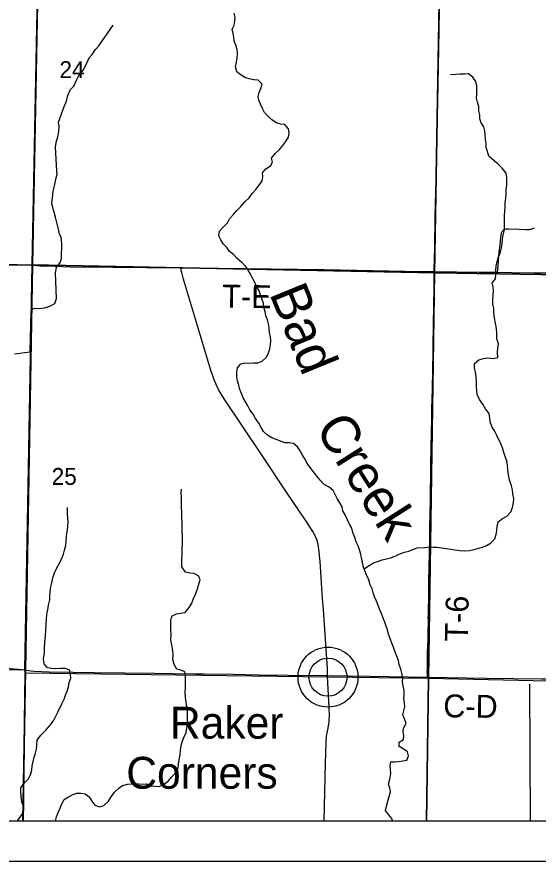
# Model space of a CAD drawing. Extents: x 0 to 42, y 0 to 22.
# Drawn here: x 6.167 to 7.46, y 14 to 16.093 of the extents above; entities that cross this region are included whole.
import ezdxf

# ---------------------------------------------------------------- set-up
doc = ezdxf.new("R2010")
doc.units = 0
for name, color, linetype in [('Default', 7, 'Continuous'), ('GM_X_County_Road', 7, 'Continuous'), ('GM_X_County_Road_Text', 7, 'Continuous'), ('GM_X_Interchange_Ramps', 7, 'Continuous'), ('GM_X_Minor_River', 7, 'Continuous'), ('GM_X_Minor_River_Text', 7, 'Continuous'), ('GM_X_Section', 7, 'Continuous'), ('GM_X_Section_Text', 7, 'Continuous'), ('GM_X_Township_Road', 7, 'Continuous'), ('GM_X_Township_Road_Text', 7, 'Continuous'), ('GM_X_Unincorporated', 7, 'Continuous'), ('GM_X_Unincorporated_Location', 7, 'Continuous'), ('GM_X_Unincorporated_Text', 7, 'Continuous'), ('SH_Data', 7, 'Continuous')]:
    doc.layers.add(name, color=color, linetype=linetype)

msp = doc.modelspace()

# ---------------------------------------------------------------- linework, layer by layer
at = {"layer": 'Default'}
for points in [[(5.1749, 14.1), (6.1826, 14.1), (6.1876, 14.466), (6.1871, 14.4739), (5.1819, 14.4731)], [(6.1826, 14.1), (7.1834, 14.1), (7.1882, 14.4532), (6.1876, 14.466)], [(7.1834, 14.1), (8.1861, 14.1), (8.1913, 14.4319), (7.6712, 14.4424), (7.1882, 14.4532)]]:
    msp.add_lwpolyline(points, close=True, dxfattribs=at)
at = {"layer": 'GM_X_County_Road'}
for points in [[(6.0728, 15.481), (6.1062, 15.4808), (6.131, 15.4805), (6.1684, 15.4792), (6.2065, 15.4773)], [(6.2065, 15.4773), (6.2244, 15.4764), (6.2618, 15.475), (6.2992, 15.4739), (6.4052, 15.4729), (6.5744, 15.4712)], [(6.9382, 14.4599), (6.9375, 14.4779), (6.929, 14.6113), (6.9272, 14.6338), (6.9258, 14.65), (6.9197, 14.743), (6.9165, 14.7739), (6.9144, 14.786), (6.911, 14.7978), (6.9076, 14.8064), (6.9017, 14.8172), (6.8849, 14.8433), (6.8674, 14.8689), (6.8375, 14.9124), (6.7738, 15.0082), (6.6818, 15.1465), (6.6686, 15.1676), (6.6614, 15.1815), (6.6567, 15.193), (6.648, 15.2197), (6.5806, 15.4428), (6.5761, 15.4592), (6.5749, 15.4635), (6.5747, 15.4653), (6.5745, 15.4671), (6.5744, 15.4692), (6.5744, 15.4712)], [(5.9383, 14.4777), (6.0367, 14.4782), (6.1238, 14.4786), (6.1393, 14.4782), (6.1611, 14.4767), (6.1797, 14.4748), (6.1885, 14.4738)], [(6.1885, 14.4738), (6.2105, 14.4714), (6.2291, 14.4699), (6.2477, 14.4692), (6.3067, 14.4683), (6.3596, 14.4677), (6.5087, 14.4658), (6.5554, 14.4655), (6.6113, 14.4646), (6.633, 14.464), (6.7045, 14.4632), (6.7667, 14.4623), (6.8413, 14.4611), (6.9345, 14.46), (6.9382, 14.4599)], [(6.93, 14.1), (6.9307, 14.1363), (6.933, 14.2418), (6.9345, 14.2936), (6.9348, 14.3009), (6.9351, 14.3058), (6.9355, 14.3095), (6.9385, 14.3252), (6.9414, 14.3398), (6.942, 14.3453), (6.9424, 14.3505), (6.9425, 14.3591), (6.9419, 14.3808), (6.9388, 14.4417), (6.9382, 14.4599)], [(6.9382, 14.4599), (7.0431, 14.4582), (7.1857, 14.4561)], [(7.1857, 14.4561), (7.2357, 14.4554), (7.3321, 14.4538), (7.4004, 14.4526), (7.4687, 14.4518), (7.478, 14.4516), (7.4904, 14.4511), (7.5991, 14.4495), (7.6551, 14.4487), (7.6695, 14.4487)]]:
    msp.add_lwpolyline(points, dxfattribs=at)
at = {"layer": 'GM_X_Interchange_Ramps'}
for points in [[(2.1, 18.5138), (2.1, 14.1), (6.182, 14.1), (6.1883, 14.4744), (6.2063, 15.4779), (6.2205, 16.2146)], [(6.2205, 16.2146), (6.2063, 15.4779), (6.1883, 14.4744), (6.182, 14.1), (8.9, 14.1), (8.9, 18.4589)]]:
    msp.add_lwpolyline(points, dxfattribs=at)
at = {"layer": 'GM_X_Minor_River'}
msp.add_line((7.4413, 14.1), (7.4401, 14.4386), dxfattribs=at)
for points in [[(6.6685, 15.5504), (6.6702, 15.5617), (6.6791, 15.5722), (6.6896, 15.5826), (6.6951, 15.5928), (6.704, 15.6028), (6.7125, 15.6125), (6.723, 15.623), (6.733, 15.6345), (6.7435, 15.6449), (6.7513, 15.655), (6.7598, 15.6651), (6.7683, 15.676), (6.7758, 15.6868), (6.7771, 15.697), (6.7769, 15.7065), (6.7847, 15.7166), (6.7962, 15.7236), (6.8013, 15.7334), (6.7992, 15.7429), (6.8078, 15.7545), (6.819, 15.7642), (6.8271, 15.7743), (6.8349, 15.7843), (6.8408, 15.7952), (6.8429, 15.8058), (6.8408, 15.8157), (6.8323, 15.8265), (6.8221, 15.8275), (6.8112, 15.8308), (6.7996, 15.8382), (6.7896, 15.8468), (6.7818, 15.8564), (6.7767, 15.8664), (6.7716, 15.8771), (6.7676, 15.8867), (6.7659, 15.8962), (6.7684, 15.9061), (6.7728, 15.9158), (6.776, 15.9264), (6.766, 15.9361), (6.755, 15.9375), (6.7433, 15.94), (6.7331, 15.9432), (6.7234, 15.9491), (6.7133, 15.9573), (6.7094, 15.9695), (6.7119, 15.9812), (6.714, 15.9911), (6.7146, 16.0024), (6.7141, 16.0127), (6.7101, 16.0234), (6.7061, 16.033), (6.7052, 16.0429), (6.7035, 16.0524), (6.7014, 16.0627), (6.7062, 16.0729), (6.7083, 16.0831), (6.7088, 16.0925), (6.706, 16.1025)], [(6.1613, 15.2576), (6.2001, 15.2625), (6.2029, 15.3638), (6.2045, 15.3683), (6.2129, 15.3712), (6.2228, 15.3706), (6.2357, 15.3715), (6.2494, 15.3758), (6.2616, 15.3824), (6.2653, 15.3948), (6.2628, 15.4583), (6.2653, 15.4715), (6.2747, 15.4839), (6.2779, 15.4945), (6.2786, 15.5313), (6.2771, 15.5473), (6.2727, 15.5542), (6.2706, 15.5671), (6.2675, 15.5801), (6.2633, 15.5965), (6.2586, 15.6114), (6.2541, 15.6301), (6.2577, 15.6612), (6.261, 15.6744), (6.264, 15.691), (6.2673, 15.7031), (6.2667, 15.7104), (6.265, 15.7411), (6.263, 15.7704), (6.2647, 15.7818), (6.2688, 15.7961), (6.2713, 15.8094), (6.2719, 15.8215), (6.2703, 15.8322), (6.2847, 15.8714), (6.2906, 15.8845), (6.2939, 15.8981), (6.3003, 15.9132), (6.3088, 15.9218), (6.3155, 15.9364), (6.3207, 15.9481), (6.3316, 15.9612), (6.3398, 15.977), (6.3466, 15.992), (6.3543, 16.0002), (6.3621, 16.0122), (6.3703, 16.0219), (6.4058, 16.0728)], [(7.3735, 15.5521), (7.3764, 15.5619), (7.3766, 15.573), (7.3772, 15.5874), (7.3771, 15.6003), (7.3781, 15.6105), (7.3787, 15.6215), (7.3782, 15.6333), (7.3799, 15.6431), (7.3809, 15.6549), (7.3814, 15.6647), (7.3824, 15.6757), (7.3826, 15.6856), (7.3824, 15.6951), (7.3807, 15.7058), (7.3711, 15.7181), (7.3615, 15.7278), (7.3514, 15.7364), (7.3384, 15.748), (7.3345, 15.7595), (7.3316, 15.7698), (7.3318, 15.7797), (7.3301, 15.7896), (7.3289, 15.801), (7.3283, 15.8105), (7.3255, 15.8204), (7.3188, 15.8304), (7.3156, 15.8407), (7.3155, 15.8506), (7.3134, 15.8601), (7.3132, 15.8712), (7.31, 15.8815), (7.3079, 15.8918), (7.3085, 15.902), (7.308, 15.9115), (7.3082, 15.9225), (7.3057, 15.9328), (7.2984, 15.944), (7.2876, 15.9522), (7.2777, 15.9509), (7.2667, 15.9511), (7.2561, 15.9505), (7.2466, 15.95), (7.2428, 15.9508)], [(7.072, 14.6138), (7.0677, 14.6234), (7.0634, 14.6341), (7.0594, 14.6449), (7.0547, 14.6552), (7.0515, 14.6651), (7.0483, 14.6755), (7.0436, 14.6854), (7.04, 14.6973), (7.035, 14.7099), (7.0306, 14.7195), (7.0267, 14.7313), (7.0246, 14.742), (7.0225, 14.7515), (7.0208, 14.7614), (7.0176, 14.7718), (7.014, 14.7817), (7.0089, 14.7913), (7.0058, 14.8028), (7.0003, 14.8146), (6.9979, 14.8253), (6.9928, 14.8353), (6.9877, 14.846), (6.9815, 14.8583), (6.9756, 14.8683), (6.9739, 14.8782), (6.9681, 14.8882), (6.9622, 14.8989), (6.9568, 14.9093), (6.952, 14.9193), (6.9416, 14.9275), (6.9296, 14.9342), (6.9196, 14.9446), (6.9114, 14.9543), (6.9037, 14.9643), (6.8948, 14.9763), (6.8867, 14.9874), (6.8824, 14.997), (6.8758, 15.0066), (6.8703, 15.0174), (6.8637, 15.027), (6.8532, 15.0352), (6.843, 15.0373), (6.8328, 15.0375), (6.8215, 15.0415), (6.8106, 15.0455), (6.8001, 15.0499), (6.7892, 15.0558), (6.7792, 15.0655), (6.7733, 15.0751), (6.7675, 15.0859), (6.7594, 15.0975), (6.7535, 15.1086), (6.745, 15.119), (6.7399, 15.1286), (6.7341, 15.139), (6.7286, 15.1486), (6.7246, 15.1597), (6.7207, 15.1696), (6.7175, 15.1803), (6.715, 15.191), (6.7133, 15.2005), (6.7132, 15.2123), (6.7146, 15.2229), (6.7231, 15.233), (6.733, 15.2358), (6.7436, 15.2348), (6.7546, 15.2354), (6.7652, 15.2359), (6.7759, 15.2399), (6.7855, 15.2484), (6.791, 15.2582), (6.7951, 15.2699), (6.7964, 15.2805), (6.797, 15.29), (6.7964, 15.301), (6.7944, 15.3109), (6.7935, 15.3227), (6.7914, 15.3326), (6.7893, 15.3421), (6.7853, 15.3517), (6.7829, 15.3616), (6.7801, 15.3735), (6.7788, 15.3834), (6.7748, 15.3941), (6.772, 15.404), (6.7684, 15.414), (6.7622, 15.4243), (6.7578, 15.4343), (6.7527, 15.4439), (6.7472, 15.455), (6.741, 15.465), (6.7355, 15.4746), (6.7258, 15.4832), (6.7147, 15.4933), (6.705, 15.5041), (6.695, 15.5115), (6.688, 15.5211), (6.6791, 15.5308), (6.6732, 15.5404), (6.6685, 15.5504)], [(7.0296, 14.7252), (7.0411, 14.7333), (7.0522, 14.7399), (7.0618, 14.7432), (7.0736, 14.7471), (7.0846, 14.7495), (7.0941, 14.752), (7.106, 14.7563), (7.1159, 14.7611), (7.1285, 14.7657), (7.1399, 14.7689), (7.1495, 14.7725), (7.1606, 14.7765), (7.1795, 14.7776), (7.1898, 14.7789), (7.1996, 14.7787), (7.2102, 14.7781), (7.2219, 14.7771), (7.2329, 14.775), (7.2435, 14.7737), (7.2548, 14.7719), (7.2661, 14.7698), (7.2779, 14.7696), (7.2904, 14.7701), (7.3018, 14.7729), (7.3121, 14.7757), (7.322, 14.7785), (7.3323, 14.7829), (7.3419, 14.7884), (7.3527, 14.7992), (7.3559, 14.8098), (7.358, 14.8196), (7.359, 14.8294), (7.3611, 14.8416), (7.3723, 14.8493), (7.3826, 14.8555), (7.3923, 14.866), (7.3971, 14.8765), (7.3992, 14.889), (7.3998, 14.8989), (7.3978, 14.9111), (7.3968, 14.9206), (7.394, 14.9305), (7.3894, 14.9454), (7.3866, 14.958), (7.3849, 14.9698), (7.3844, 14.9816), (7.3827, 14.9922), (7.3784, 15.0033), (7.3756, 15.0133), (7.3716, 15.0247), (7.368, 15.0347), (7.3582, 15.0554), (7.352, 15.0673), (7.3458, 15.078), (7.3411, 15.0892), (7.3409, 15.0994), (7.3392, 15.1097), (7.33, 15.1217), (7.3234, 15.1332), (7.3149, 15.1447), (7.3095, 15.1566), (7.3086, 15.1665), (7.3077, 15.1779), (7.3071, 15.1886), (7.3066, 15.2007), (7.3046, 15.2122), (7.3029, 15.2224), (7.3023, 15.2335), (7.3135, 15.2427), (7.3249, 15.2459), (7.3348, 15.2476), (7.3496, 15.2466), (7.3606, 15.2486), (7.3597, 15.2608), (7.3603, 15.2718), (7.3617, 15.2828), (7.3578, 15.2954), (7.358, 15.309), (7.3567, 15.3208), (7.3544, 15.3338), (7.3523, 15.3471), (7.3507, 15.3593), (7.3502, 15.37), (7.3481, 15.3806), (7.3483, 15.3916), (7.3489, 15.4034), (7.3495, 15.4144), (7.349, 15.4239), (7.3461, 15.4338), (7.3547, 15.4439), (7.3556, 15.4545), (7.3558, 15.4648), (7.3564, 15.475), (7.3586, 15.4864), (7.3622, 15.4984), (7.367, 15.5097), (7.3691, 15.5211), (7.3712, 15.5317), (7.3718, 15.5423), (7.3735, 15.5521)], [(6.5776, 14.7605), (6.5784, 14.8034), (6.5776, 14.8171), (6.5771, 14.8308), (6.5773, 14.8402), (6.5764, 14.8517), (6.5762, 14.8612), (6.5758, 14.8809), (6.5757, 14.8927), (6.5755, 14.9037), (6.575, 14.9132), (6.5755, 14.9223)], [(6.1692, 14.1), (6.1715, 14.103), (6.1789, 14.1143), (6.1844, 14.1248), (6.1835, 14.1362), (6.1795, 14.1465), (6.1783, 14.161), (6.177, 14.1716), (6.1772, 14.1819), (6.1846, 14.1927), (6.1955, 14.2035), (6.201, 14.2141), (6.2046, 14.2254), (6.2052, 14.2364), (6.2077, 14.2473), (6.2106, 14.2575), (6.2131, 14.2677), (6.2159, 14.2779), (6.2169, 14.2893), (6.2179, 14.3003), (6.2268, 14.3123), (6.2392, 14.3245), (6.2508, 14.3376), (6.2586, 14.3492), (6.2638, 14.359), (6.2693, 14.3695), (6.2788, 14.3898), (6.2847, 14.4019), (6.2883, 14.4117), (6.2923, 14.4214), (6.2952, 14.4316), (6.2973, 14.4426), (6.3013, 14.4535), (6.3007, 14.4638), (6.2987, 14.4737), (6.287, 14.4774), (6.2753, 14.478), (6.2631, 14.4767), (6.2529, 14.4773), (6.2431, 14.4794), (6.2346, 14.4894), (6.2337, 14.5024), (6.2355, 14.5164), (6.2361, 14.527), (6.2368, 14.5433), (6.2386, 14.5585), (6.2389, 14.5729), (6.2399, 14.5862), (6.241, 14.5998), (6.242, 14.6112), (6.2437, 14.6233), (6.2454, 14.6343), (6.2491, 14.6475), (6.2489, 14.657), (6.2499, 14.6676), (6.2517, 14.6805), (6.2538, 14.6903), (6.2567, 14.702), (6.2603, 14.7145), (6.2655, 14.7258), (6.2729, 14.7385), (6.2789, 14.7509), (6.2829, 14.7611), (6.2857, 14.7709), (6.289, 14.7823), (6.2896, 14.7933), (6.2902, 14.8065), (6.2928, 14.8205), (6.2937, 14.8308), (6.2947, 14.841), (6.2934, 14.8505), (6.2932, 14.8604), (6.2926, 14.8699), (6.2931, 14.8767)], [(6.2633, 14.1), (6.2652, 14.1095), (6.2707, 14.1219), (6.2751, 14.1317), (6.2787, 14.1422), (6.285, 14.1524), (6.2954, 14.1598), (6.3065, 14.1652), (6.316, 14.1681), (6.3258, 14.1683), (6.3364, 14.1665), (6.3465, 14.1595), (6.3535, 14.1483), (6.3605, 14.1387), (6.3721, 14.1347), (6.3832, 14.1379), (6.3948, 14.149), (6.4011, 14.1595), (6.4092, 14.1708), (6.42, 14.1808), (6.4296, 14.1871), (6.4418, 14.1906), (6.4528, 14.1915), (6.4635, 14.1928), (6.4775, 14.191), (6.4888, 14.1919), (6.4986, 14.1868), (6.5092, 14.1855), (6.5201, 14.1849), (6.5312, 14.1899), (6.5428, 14.1981), (6.5517, 14.2093), (6.5625, 14.2205), (6.5677, 14.2306), (6.5686, 14.2408), (6.57, 14.2514), (6.5725, 14.2639), (6.5735, 14.2749), (6.5752, 14.2863), (6.5777, 14.2961), (6.5817, 14.3066), (6.5869, 14.3187), (6.5886, 14.3297), (6.5903, 14.3399), (6.5909, 14.3501), (6.5904, 14.3619), (6.5902, 14.3733), (6.5893, 14.3828), (6.5876, 14.3942), (6.5856, 14.4057), (6.5847, 14.4178), (6.5857, 14.4296), (6.5859, 14.4398), (6.5857, 14.4493), (6.5859, 14.46), (6.5842, 14.4695), (6.5741, 14.4735), (6.5639, 14.476), (6.5573, 14.4875), (6.5541, 14.4997), (6.5548, 14.5126), (6.5538, 14.5221), (6.5518, 14.5351), (6.5494, 14.5488), (6.5501, 14.5617), (6.5492, 14.5731), (6.549, 14.5845), (6.5493, 14.5966), (6.5514, 14.6076), (6.5636, 14.6134), (6.5743, 14.6144), (6.5849, 14.6161), (6.595, 14.6288), (6.6017, 14.64), (6.6057, 14.6513), (6.6109, 14.6638), (6.6153, 14.6751), (6.6189, 14.6864), (6.6218, 14.6977), (6.6178, 14.7073), (6.6062, 14.7128), (6.596, 14.7142), (6.5858, 14.7167), (6.5766, 14.7298), (6.5764, 14.7396), (6.5766, 14.7495), (6.5776, 14.7605)], [(7.0989, 14.1), (7.0978, 14.1056), (7.0889, 14.1157), (7.0819, 14.1253), (7.084, 14.1363), (7.0873, 14.1488), (7.0909, 14.1605), (7.0938, 14.1714), (7.0925, 14.1813), (7.0893, 14.1912), (7.0922, 14.2033), (7.0947, 14.217), (7.0945, 14.2268), (7.0936, 14.2363), (7.0946, 14.2462), (7.1044, 14.246), (7.1139, 14.2466), (7.1245, 14.2483), (7.1348, 14.2507), (7.1392, 14.2612), (7.1364, 14.2712), (7.1259, 14.2786), (7.1154, 14.2841), (7.116, 14.2948), (7.1264, 14.3014), (7.1269, 14.3109), (7.1256, 14.3204), (7.1262, 14.3299), (7.1328, 14.3411), (7.1285, 14.3526), (7.1249, 14.3625), (7.127, 14.3728), (7.1299, 14.3826), (7.1286, 14.3921), (7.1276, 14.4031), (7.1282, 14.413), (7.1277, 14.4232), (7.1256, 14.4339), (7.1239, 14.4442), (7.1245, 14.4544), (7.1221, 14.4659), (7.12, 14.4758), (7.1157, 14.4873), (7.1144, 14.4976), (7.1097, 14.5083), (7.1057, 14.5179), (7.1025, 14.5278), (7.0978, 14.5404), (7.0931, 14.5519), (7.0896, 14.563), (7.0864, 14.5733), (7.0832, 14.5829), (7.0803, 14.5928), (7.076, 14.6028), (7.072, 14.6138)]]:
    msp.add_lwpolyline(points, dxfattribs=at)
at = {"layer": 'GM_X_Section'}
for points in [[(6.224, 16.494), (6.2249, 16.4863), (6.2056, 15.4786), (5.2026, 15.4687), (5.2156, 16.4769), (5.6923, 16.4799)], [(6.2249, 16.4863), (7.2205, 16.4649), (7.2034, 15.459), (6.2056, 15.4786)], [(7.2205, 16.4649), (8.2267, 16.4466), (8.207, 15.4431), (7.2034, 15.459)], [(6.2056, 15.4786), (6.1871, 14.4739), (5.1819, 14.4731), (5.2026, 15.4687)], [(6.2056, 15.4786), (7.2034, 15.459), (7.1882, 14.4532), (6.1876, 14.466), (6.1871, 14.4739)], [(7.2034, 15.459), (8.207, 15.4431), (8.1913, 14.4319), (7.6712, 14.4424), (7.1882, 14.4532)]]:
    msp.add_lwpolyline(points, close=True, dxfattribs=at)
at = {"layer": 'GM_X_Township_Road'}
for points in [[(7.2026, 15.4619), (7.2028, 15.4707), (7.2034, 15.4889), (7.2034, 15.4983), (7.2039, 15.5168), (7.2052, 15.6006), (7.206, 15.6285), (7.2075, 15.6907), (7.2088, 15.7334), (7.2085, 15.7458), (7.2088, 15.7582), (7.2095, 15.7955), (7.2115, 15.8794), (7.2125, 15.9292), (7.2139, 16.0131), (7.215, 16.0628), (7.2156, 16.1095), (7.2167, 16.1467), (7.2178, 16.216)], [(7.3594, 15.46), (7.36, 15.4664), (7.364, 15.5097), (7.3663, 15.5279), (7.368, 15.5464), (7.3683, 15.5501), (7.3689, 15.5539), (7.3694, 15.5558), (7.3698, 15.5575), (7.3704, 15.5595), (7.371, 15.5608), (7.372, 15.562), (7.3731, 15.5632), (7.3747, 15.5646)], [(7.3747, 15.5646), (7.3764, 15.5656), (7.3779, 15.5665), (7.3797, 15.567), (7.3817, 15.5674), (7.3844, 15.5678), (7.3878, 15.5679), (7.4121, 15.567), (7.43, 15.5663), (7.4348, 15.5662), (7.4379, 15.5664), (7.4403, 15.5668), (7.4428, 15.5671), (7.4455, 15.568), (7.4476, 15.569), (7.4511, 15.5706)], [(6.0728, 15.481), (6.1062, 15.4808), (6.131, 15.4805), (6.1684, 15.4792), (6.2065, 15.4773)], [(6.2065, 15.4773), (6.2244, 15.4764), (6.2618, 15.475), (6.2992, 15.4739), (6.4052, 15.4729), (6.5744, 15.4712)], [(6.5744, 15.4712), (6.5808, 15.4712), (6.5961, 15.4712), (6.6675, 15.4706), (6.9286, 15.4666), (7.1711, 15.4623), (7.2026, 15.4619)], [(7.1857, 14.4561), (7.1856, 14.4641), (7.1855, 14.4673), (7.1856, 14.4765), (7.1862, 14.5169), (7.1874, 14.548), (7.1873, 14.5635), (7.1881, 14.597), (7.188, 14.6032), (7.1882, 14.6093), (7.1885, 14.6187), (7.1886, 14.631), (7.1892, 14.6433), (7.1893, 14.6526), (7.1891, 14.6611), (7.1894, 14.6766), (7.1895, 14.6921), (7.1901, 14.7294), (7.1906, 14.7604), (7.1915, 14.8008), (7.1918, 14.8226), (7.1924, 14.8661), (7.193, 14.894), (7.1943, 14.978), (7.195, 15.0277), (7.1964, 15.0961), (7.197, 15.1209), (7.1981, 15.1707), (7.2, 15.2629), (7.2001, 15.2754), (7.2007, 15.3313), (7.2015, 15.3748), (7.2021, 15.4215), (7.2026, 15.4619)], [(7.2026, 15.4619), (7.3141, 15.4606), (7.3594, 15.46)], [(7.3594, 15.46), (7.3949, 15.4595), (7.4508, 15.4589), (7.5191, 15.4585), (7.5593, 15.4577), (7.5675, 15.4576)]]:
    msp.add_lwpolyline(points, dxfattribs=at)
at = {"layer": 'GM_X_Unincorporated'}
for radius in [0.0744, 0.0472]:
    msp.add_circle((6.9391, 14.4562), radius, dxfattribs=at)
at = {"layer": 'GM_X_Unincorporated_Location'}
msp.add_line((6.9391, 14.4562), (6.9391, 14.4562), dxfattribs=at)
at = {"layer": 'SH_Data'}
for p, q in [((2.1, 14.1), (8.9, 14.1)), ((2, 14), (9, 14))]:
    msp.add_line(p, q, dxfattribs=at)

# ---------------------------------------------------------------- texts
at = {"layer": 'GM_X_County_Road_Text'}
msp.add_text('C-D', height=0.05682, rotation=359.2081, dxfattribs=at).set_placement((7.2247, 14.3567))
at = {"layer": 'GM_X_Minor_River_Text'}
for s, height, rotation, p in [('Bad', 0.09477, 292.2535, (6.7927, 15.4078)), ('Creek', 0.09476, 302.4878, (6.9052, 15.0728))]:
    msp.add_text(s, height=height, rotation=rotation, dxfattribs=at).set_placement(p)
at = {"layer": 'GM_X_Section_Text'}
for s, p in [('24', (6.2729, 15.9416)), ('25', (6.2537, 14.9329))]:
    msp.add_text(s, height=0.04186, rotation=0, dxfattribs=at).set_placement(p)
at = {"layer": 'GM_X_Township_Road_Text'}
for s, rotation, p in [('T-E', 359.1191, (6.6764, 15.3727)), ('T-6', 88.6255, (7.2856, 14.5437))]:
    msp.add_text(s, height=0.05682, rotation=rotation, dxfattribs=at).set_placement(p)
at = {"layer": 'GM_X_Unincorporated_Text'}
for s, p in [('Raker', (6.547, 14.3037)), ('Corners', (6.4387, 14.1795))]:
    msp.add_text(s, height=0.07898, rotation=0, dxfattribs=at).set_placement(p)

doc.saveas('drawing.dxf')
